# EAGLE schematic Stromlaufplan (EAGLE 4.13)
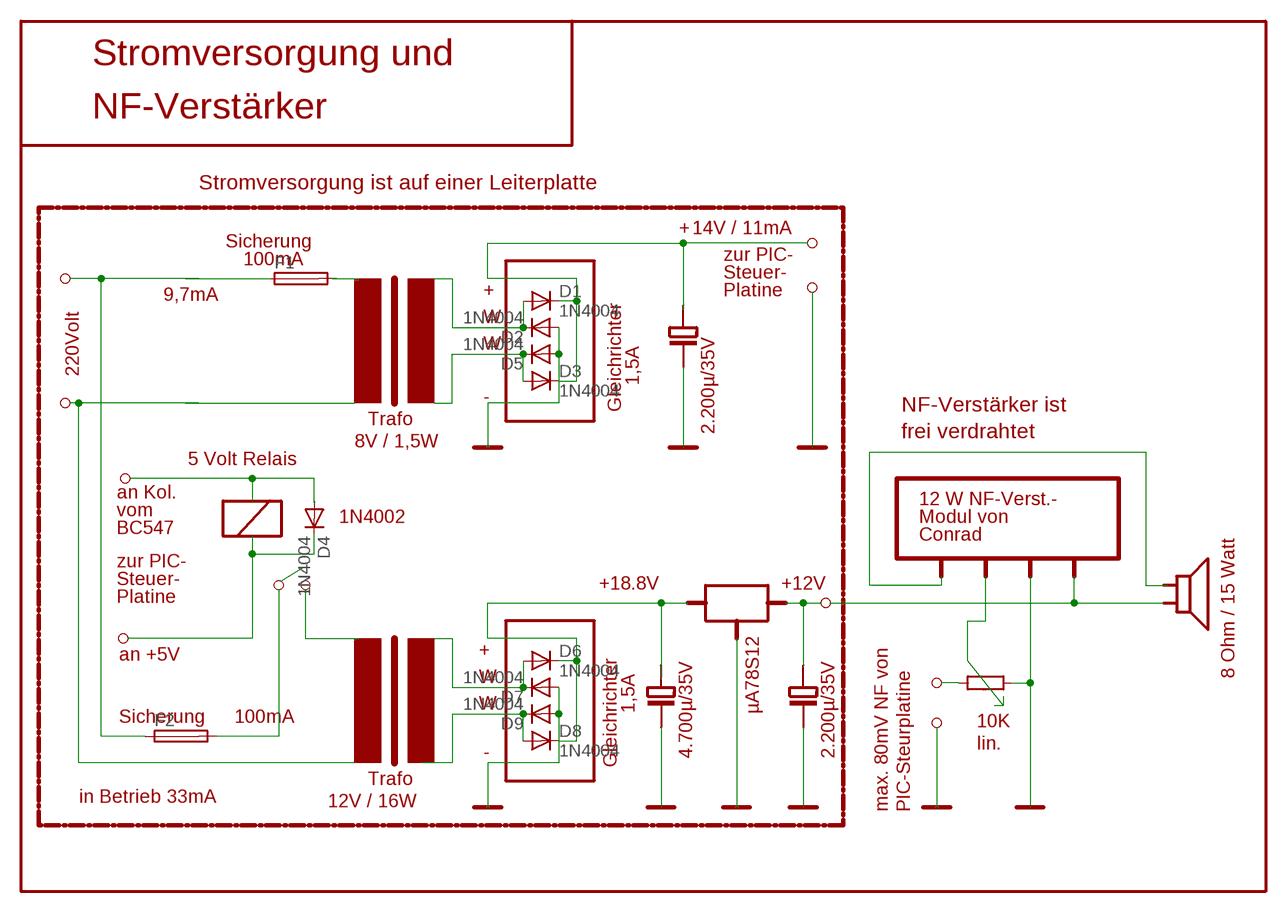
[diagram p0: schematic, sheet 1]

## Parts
D1  1N4004  [DO41-10]
D2  1N4004  [DO41-10]
D3  1N4004  [DO41-10]
D4  1N4004  [DO41-10]
D5  1N4004  [DO41-10]
D6  1N4004  [DO41-10]
D7  1N4004  [DO41-10]
D8  1N4004  [DO41-10]
D9  1N4004  [DO41-10]
F1  19559  [19559]
F2  19559  [19559]

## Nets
N$1: F1.2
N$4: F1.1
N$5: F2.1
N$7: D1.A D2.C
N$8: D3.A D5.C
N$9: D6.A D7.C
N$10: D1.C D3.C
N$11: D2.A D5.A
N$12: D8.A D9.C
N$13: D6.C D8.C
N$14: D7.A D9.A
N$28: F2.2
Unconnected: D4.A D4.C

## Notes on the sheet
- Stromversorgung und
- NF-Verstärker
- Stromversorgung ist auf einer Leiterplatte
- + | 14V / 11mA
- Sicherung
- 100mA | zur PIC-
- Steuer-
- 9,7mA | + | Platine
- W
- W
- 220Volt
- 1,5A
- -
- Gleichrichter | NF-Verstärker ist
- Trafo
- 2.200µ/35V | frei verdrahtet
- 8V / 1,5W
- 5 Volt Relais
- an Kol.
- 12 W NF-Verst.-
- vom
- 1N4002 | Modul von
- BC547
- Conrad
- zur PIC-
- Steuer- | +18.8V | +12V
- Platine
- an +5V | +
- 1,5A | 8 Ohm / 15 Watt
- W
- W | µA78S12
- Sicherung | 100mA | 10K
- lin.
- - | 4.700µ/35V | 2.200µ/35V
- Gleichrichter
- Trafo
- in Betrieb 33mA | 12V / 16W
- max. 80mV NF von | PIC-Steurplatine

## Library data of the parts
D1-D9 = diode:1N4004: DIODE
F1 F2 = fuse:19559: FUSE HOLDER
